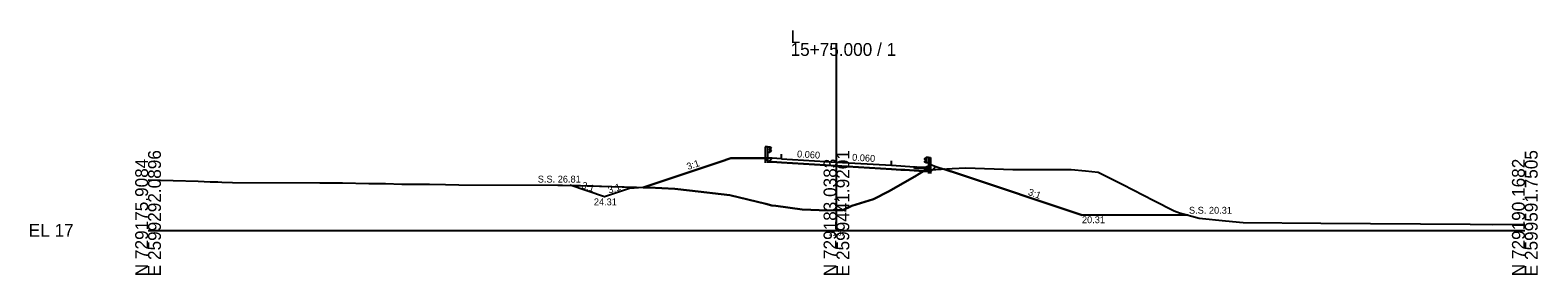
# Model space of a CAD drawing. Extents: x -26 to 3303, y -10 to 9555.
# Drawn here: x 974.3 to 1302.8, y 1490.3 to 1543.6 of the extents above; entities that cross this region are included whole.
import ezdxf

# ---------------------------------------------------------------- set-up
doc = ezdxf.new("R2010")
doc.units = 0
for name, color, linetype in [('Exist Cross Section Cell', 7, 'Continuous'), ('Exist XS Center Line Elevation Label', 7, 'Continuous'), ('Exist XS Ground Line', 7, 'Continuous'), ('Prop XS Ditch Slope Text', 7, 'Continuous'), ('Prop XS Ditch Standard Text', 7, 'Continuous'), ('Prop XS Dump Level', 7, 'Continuous'), ('Prop XS Earthwork Shape', 7, 'Continuous'), ('Prop XS EOT Tick Mark', 7, 'Continuous'), ('Prop XS Finish Grade', 7, 'Continuous'), ('Prop XS Finish Grade Earthwork', 7, 'Continuous'), ('Prop XS Finish Grade Paved Shoulder', 7, 'Continuous'), ('Prop XS Finish Grade Pavement', 7, 'Continuous'), ('Prop XS Pvmt Edge Slope', 7, 'Continuous'), ('Prop XS SE Text', 7, 'Continuous'), ('Prop XS Side Slope Text', 7, 'Continuous'), ('Prop XS SS Elevation Text', 7, 'Continuous'), ('Prop XS Subgrade Earthwork', 7, 'Continuous'), ('Typical Curb CELL', 7, 'Continuous'), ('Typical Guardrail CELL', 7, 'Continuous')]:
    doc.layers.add(name, color=color, linetype=linetype)

msp = doc.modelspace()

# ---------------------------------------------------------------- linework, layer by layer
at = {"layer": 'Exist Cross Section Cell'}
for p, q in [((1150, 1500), (1150, 1540.81)), ((1000, 1500), (1150, 1500)), ((1150, 1500), (1300, 1500))]:
    msp.add_line(p, q, dxfattribs=at)
at = {"layer": 'Exist XS Ground Line'}
msp.add_lwpolyline([(1000, 1511.02), (1010.89, 1510.68), (1013.54, 1510.6), (1014.29, 1510.58), (1015.19, 1510.55), (1016.11, 1510.48), (1018.39, 1510.42), (1037.45, 1510.35), (1038.49, 1510.35), (1039.09, 1510.35), (1042.36, 1510.33), (1048.13, 1510.24), (1051.75, 1510.18), (1055.31, 1510.05), (1058.93, 1510.04), (1061.34, 1510.05), (1064.82, 1510), (1067.7, 1509.93), (1089.28, 1509.88), (1090.3, 1509.86), (1109.09, 1509.33), (1114.77, 1509.03), (1118.01, 1508.65), (1126.76, 1507.7), (1134.58, 1505.76), (1135.89, 1505.44), (1136.76, 1505.35), (1142.56, 1504.57), (1148.1, 1504.33), (1150, 1504.37), (1151.39, 1504.4), (1153.34, 1505.31), (1158.04, 1506.77), (1161.35, 1508.44), (1167.07, 1511.75), (1169.26, 1513.11), (1175.22, 1513.45), (1178.22, 1513.6), (1188.44, 1513.26), (1189.19, 1513.25), (1192.52, 1513.26), (1201.16, 1513.27), (1204.27, 1512.96), (1207.06, 1512.68), (1212.42, 1509.96), (1219.19, 1506.48), (1223.62, 1504.22), (1224.76, 1503.81), (1229.05, 1502.66), (1234.75, 1502.1), (1238.63, 1501.69), (1255.53, 1501.57), (1288.1, 1501.36), (1293.01, 1501.26), (1300, 1501.36)], dxfattribs=at)
at = {"layer": 'Prop XS Dump Level'}
for p, q in [((1138, 1515.61), (1150, 1514.89)), ((1150, 1514.89), (1162, 1514.17))]:
    msp.add_line(p, q, dxfattribs=at)
at = {"layer": 'Prop XS Earthwork Shape'}
for points in [[(1107.88, 1509.36), (1109.09, 1509.33), (1114.77, 1509.03), (1118.01, 1508.65), (1126.76, 1507.7), (1134.58, 1505.76), (1135.89, 1505.44), (1136.76, 1505.35), (1142.56, 1504.57), (1148.1, 1504.33), (1150, 1504.37), (1151.39, 1504.4), (1153.34, 1505.31), (1158.04, 1506.77), (1161.35, 1508.44), (1167.07, 1511.75), (1168.96, 1512.92), (1164.89, 1513.17), (1164, 1513.22), (1162, 1513.34), (1150, 1514.06), (1138, 1514.78), (1136, 1514.9), (1135.21, 1514.95), (1134.43, 1515.73), (1127, 1515.73), (1124.64, 1514.95)], [(1164, 1513.22), (1164.89, 1513.17), (1168.96, 1512.92), (1167.07, 1511.75), (1161.35, 1508.44), (1158.04, 1506.77), (1153.34, 1505.31), (1151.39, 1504.4), (1150, 1504.37), (1148.1, 1504.33), (1142.56, 1504.57), (1136.76, 1505.35), (1135.89, 1505.44), (1134.58, 1505.76), (1126.76, 1507.7), (1118.01, 1508.65), (1114.77, 1509.03), (1109.09, 1509.33), (1107.88, 1509.36), (1124.64, 1514.95), (1127, 1515.73), (1134.43, 1515.73), (1135.21, 1514.95), (1136, 1514.9), (1138, 1514.78), (1150, 1514.06), (1162, 1513.34)], [(1168.96, 1512.92), (1170.56, 1512.83), (1170.94, 1513.21), (1169.26, 1513.11)], [(1168.96, 1512.92), (1169.26, 1513.11), (1170.94, 1513.21), (1170.56, 1512.83)], [(1170.94, 1513.21), (1171.68, 1513.94), (1173.45, 1513.35)], [(1170.94, 1513.21), (1171.68, 1513.94), (1173.45, 1513.35)], [(1173.45, 1513.35), (1175.22, 1513.45), (1178.22, 1513.6), (1188.44, 1513.26), (1189.19, 1513.25), (1192.52, 1513.26), (1201.16, 1513.27), (1204.27, 1512.96), (1207.06, 1512.68), (1212.42, 1509.96), (1219.19, 1506.48), (1223.62, 1504.22), (1224.76, 1503.81), (1226.63, 1503.31), (1203.57, 1503.31), (1176.4, 1512.37)], [(1173.45, 1513.35), (1175.22, 1513.45), (1178.22, 1513.6), (1188.44, 1513.26), (1189.19, 1513.25), (1192.52, 1513.26), (1201.16, 1513.27), (1204.27, 1512.96), (1207.06, 1512.68), (1212.42, 1509.96), (1219.19, 1506.48), (1223.62, 1504.22), (1224.76, 1503.81), (1226.63, 1503.31), (1203.57, 1503.31), (1176.4, 1512.37)], [(1091.96, 1509.81), (1107.88, 1509.36), (1104.88, 1509.11), (1099.48, 1507.31)], [(1091.96, 1509.81), (1107.88, 1509.36), (1104.88, 1509.11), (1099.48, 1507.31)]]:
    msp.add_lwpolyline(points, close=True, dxfattribs=at)
at = {"layer": 'Prop XS EOT Tick Mark'}
for p, q in [((1138, 1515.61), (1138, 1516.61)), ((1162, 1514.17), (1162, 1515.17))]:
    msp.add_line(p, q, dxfattribs=at)
at = {"layer": 'Prop XS Finish Grade'}
for p, q in [((1136, 1515.73), (1134.43, 1515.73)), ((1170.03, 1514.06), (1170.56, 1514.31)), ((1170.56, 1514.31), (1171.68, 1513.94))]:
    msp.add_line(p, q, dxfattribs=at)
at = {"layer": 'Prop XS Finish Grade Earthwork'}
for p, q in [((1124.64, 1514.95), (1107.88, 1509.36)), ((1127, 1515.73), (1124.64, 1514.95)), ((1134.43, 1515.73), (1127, 1515.73)), ((1171.68, 1513.94), (1176.4, 1512.37)), ((1176.4, 1512.37), (1203.57, 1503.31)), ((1099.48, 1507.31), (1091.96, 1509.81)), ((1104.88, 1509.11), (1099.48, 1507.31)), ((1107.88, 1509.36), (1104.88, 1509.11)), ((1226.63, 1503.31), (1203.57, 1503.31))]:
    msp.add_line(p, q, dxfattribs=at)
at = {"layer": 'Prop XS Finish Grade Paved Shoulder'}
for p, q in [((1138, 1515.61), (1136, 1515.73)), ((1162, 1514.17), (1167, 1513.87))]:
    msp.add_line(p, q, dxfattribs=at)
at = {"layer": 'Prop XS Finish Grade Pavement'}
for p, q in [((1138, 1515.61), (1150, 1514.89)), ((1150, 1514.89), (1162, 1514.17))]:
    msp.add_line(p, q, dxfattribs=at)
at = {"layer": 'Prop XS Pvmt Edge Slope'}
for p, q in [((1135.21, 1514.95), (1134.43, 1515.73)), ((1136, 1515.73), (1135.21, 1514.95)), ((1170.01, 1513.38), (1170.56, 1512.83)), ((1170.56, 1512.83), (1171.68, 1513.94))]:
    msp.add_line(p, q, dxfattribs=at)
at = {"layer": 'Prop XS Subgrade Earthwork'}
for p, q in [((1135.21, 1514.95), (1134.43, 1515.73)), ((1136, 1514.9), (1135.21, 1514.95)), ((1138, 1514.78), (1136, 1514.9)), ((1150, 1514.06), (1138, 1514.78)), ((1162, 1513.34), (1150, 1514.06)), ((1162, 1513.34), (1164, 1513.22)), ((1164, 1513.22), (1164.89, 1513.17)), ((1164.89, 1513.17), (1170.56, 1512.83)), ((1170.56, 1512.83), (1171.68, 1513.94))]:
    msp.add_line(p, q, dxfattribs=at)
at = {"layer": 'Typical Curb CELL'}
for p, q in [((1166.99, 1513.46), (1167, 1513.86)), ((1170.01, 1513.38), (1166.99, 1513.46)), ((1167, 1513.87), (1167, 1513.87)), ((1167.01, 1513.87), (1169.33, 1513.73)), ((1167.23, 1513.6), (1167.32, 1513.72)), ((1167.35, 1513.61), (1167.23, 1513.6)), ((1167.32, 1513.72), (1167.35, 1513.61)), ((1167.99, 1513.53), (1168.06, 1513.65)), ((1168.16, 1513.57), (1167.99, 1513.53)), ((1168.06, 1513.65), (1168.16, 1513.57)), ((1168.48, 1513.57), (1168.57, 1513.69)), ((1168.6, 1513.58), (1168.48, 1513.57)), ((1168.57, 1513.69), (1168.6, 1513.58)), ((1169.24, 1513.5), (1169.31, 1513.62)), ((1169.41, 1513.54), (1169.24, 1513.5)), ((1169.31, 1513.62), (1169.41, 1513.54)), ((1169.33, 1513.73), (1170.03, 1514.06)), ((1169.83, 1513.73), (1169.84, 1513.64)), ((1169.98, 1513.68), (1169.83, 1513.73)), ((1169.84, 1513.64), (1169.98, 1513.68)), ((1170.01, 1513.38), (1170.03, 1514.06))]:
    msp.add_line(p, q, dxfattribs=at)
for centre in [(1167.09, 1513.69), (1167.13, 1513.82), (1167.49, 1513.74), (1167.55, 1513.56), (1167.6, 1513.52), (1167.64, 1513.65), (1167.71, 1513.64), (1167.76, 1513.67), (1167.81, 1513.55), (1168, 1513.59), (1168.21, 1513.57), (1168.23, 1513.62), (1168.24, 1513.68), (1168.29, 1513.53), (1168.39, 1513.58), (1168.48, 1513.58), (1168.6, 1513.53), (1168.8, 1513.52), (1168.85, 1513.49), (1168.89, 1513.61), (1169.01, 1513.64), (1169.06, 1513.52), (1169.25, 1513.56), (1169.28, 1513.46), (1169.46, 1513.54), (1169.48, 1513.59), (1169.73, 1513.55), (1169.85, 1513.5), (1169.95, 1513.77)]:
    msp.add_circle(centre, 0.00802, dxfattribs=at)
msp.add_arc((1167.01, 1513.86), 0.0104, 86.5213, 178.5693, dxfattribs=at)
at = {"layer": 'Typical Guardrail CELL'}
for p, q in [((1135, 1518.22), (1134.5, 1518.22)), ((1134.5, 1518.22), (1134.5, 1515.73)), ((1135, 1518.22), (1135, 1515.73)), ((1135, 1518.22), (1135.5, 1518.22)), ((1135.5, 1518.22), (1135.5, 1517.06)), ((1135.5, 1518.22), (1135.79, 1518.02)), ((1135.5, 1517.69), (1135.79, 1517.89)), ((1135, 1515.73), (1134.5, 1515.73)), ((1134.5, 1515.73), (1134.5, 1514.73)), ((1135, 1517.06), (1135.5, 1517.06)), ((1135, 1515.73), (1135, 1514.73)), ((1135.5, 1517.64), (1135.5, 1517.69)), ((1135.5, 1517.64), (1135.5, 1517.59)), ((1135.5, 1517.59), (1135.79, 1517.39)), ((1135.5, 1517.06), (1135.79, 1517.26)), ((1169.53, 1515.84), (1169.24, 1515.64)), ((1169.53, 1515.31), (1169.24, 1515.51)), ((1169.53, 1515.21), (1169.24, 1515.01)), ((1169.53, 1514.68), (1169.24, 1514.88)), ((1170.03, 1515.84), (1169.53, 1515.84)), ((1169.53, 1515.84), (1169.53, 1514.68)), ((1169.53, 1515.26), (1169.53, 1515.31)), ((1169.53, 1515.26), (1169.53, 1515.21)), ((1170.03, 1514.68), (1169.53, 1514.68)), ((1170.03, 1515.84), (1170.03, 1513.36)), ((1170.03, 1515.84), (1170.53, 1515.84)), ((1170.53, 1515.84), (1170.53, 1513.36)), ((1170.03, 1513.36), (1170.53, 1513.36)), ((1170.03, 1513.36), (1170.03, 1512.35)), ((1170.53, 1513.36), (1170.53, 1512.35))]:
    msp.add_line(p, q, dxfattribs=at)
for centre, start, end in [((1135.74, 1517.95), 304.9888, 54.997), ((1135.74, 1517.33), 304.9634, 54.9941), ((1169.29, 1515.57), 125.003, 235.0112), ((1169.29, 1514.95), 125.0059, 235.0366)]:
    msp.add_arc(centre, 0.0776, start, end, dxfattribs=at)

# ---------------------------------------------------------------- texts
at = {"layer": 'Exist Cross Section Cell'}
for s, p in [('15+75.000 / 1', (1140, 1538.01)), ('L', (1140, 1540.81)), ('EL 17', (974, 1498.6))]:
    msp.add_text(s, height=2.8, dxfattribs=at).set_placement(p)
for s, p in [('N 729175.9084', (1000, 1490)), ('E 2599292.0896', (1002.8, 1490)), ('N 729183.0383', (1150, 1490)), ('E 2599441.9201', (1152.8, 1490)), ('N 729190.1682', (1300, 1490)), ('E 2599591.7505', (1302.8, 1490))]:
    msp.add_text(s, height=2.8, rotation=90, dxfattribs=at).set_placement(p)
at = {"layer": 'Exist XS Center Line Elevation Label'}
msp.add_text('21.37', height=1, dxfattribs=at).set_placement((1148.37, 1498.87))
at = {"layer": 'Prop XS Ditch Slope Text'}
msp.add_text('3:1', height=1.5, rotation=340.5558, dxfattribs=at).set_placement((1191.63, 1507.75))
at = {"layer": 'Prop XS Ditch Standard Text'}
msp.add_text('20.31', height=1.5, dxfattribs=at).set_placement((1203.5, 1501.56))
at = {"layer": 'Prop XS Dump Level'}
for p in [(1130, 1515.69), (1170, 1513.53), (1173, 1513.29)]:
    msp.add_text('Case1', height=0.04, dxfattribs=at).set_placement(p)
at = {"layer": 'Prop XS SE Text'}
for p in [(1141.38, 1515.91), (1153.38, 1515.19)]:
    msp.add_text('0.060', height=1.5, rotation=356.5664, dxfattribs=at).set_placement(p)
at = {"layer": 'Prop XS Side Slope Text'}
for rotation, p in [(18.4349, (1117.66, 1513.14)), (341.0185, (1094.33, 1509.24)), (18.4349, (1100.49, 1507.98))]:
    msp.add_text('3:1', height=1.5, rotation=rotation, dxfattribs=at).set_placement(p)
at = {"layer": 'Prop XS SS Elevation Text'}
for s, p in [('S.S. 26.81', (1084.92, 1510.41)), ('24.31', (1097.14, 1505.45)), ('S.S. 20.31', (1226.82, 1503.62))]:
    msp.add_text(s, height=1.5, dxfattribs=at).set_placement(p)

doc.saveas('drawing.dxf')
